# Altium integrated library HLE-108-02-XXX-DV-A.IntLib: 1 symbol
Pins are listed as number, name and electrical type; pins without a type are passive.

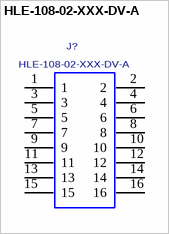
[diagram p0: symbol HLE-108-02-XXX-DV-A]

## HLE-108-02-XXX-DV-A
designator J?
Socket Assembly, Dual Row Vertical, Surface Mount, 0.100" Pitch.; MANUFACTURER: SAMTEC
footprint HLE-108-02-XXX-DV-A
pins: 1, 2, 3, 4, 5, 6, 7, 8, 9, 10, 11, 12, 13, 14, 15, 16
